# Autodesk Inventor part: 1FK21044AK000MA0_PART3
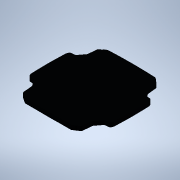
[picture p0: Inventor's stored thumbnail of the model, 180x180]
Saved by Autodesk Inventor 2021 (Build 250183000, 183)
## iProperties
Created: 2025-04
Part Number: 1FK21044AK000MA0_PART3
Material: Generic
Catalog Web Link: www.3dfindit.com
Description: -Servo synchronous motor
Document SubType Name: Modeling
Designer: psAdmin
Mass: 21.7019 g
Surface Area: 120.085 cm^2
Volume: 21.7019 cm^3
Density: 1 g/cm^3
Appearance: PSOLRGB-38-46-56
Category: PARTsolutions
Title: 1FK21044AK000MA0_PART3
Author: Cadenas PARTsolutions
Comments: Servo synchronous motor
Sending System: PARTsolutions
Preprocessor: ST-DEVELOPER v19.3
PSOL_IDENT_0: {$CADENAS_DATA/23d-libs/siemens_ag/_cat_/87/f4/1fk21044ak000ma0.prj},213 {VTYP=3D},{NB=1FK21044AK000
PSOL_IDENT_1: MA0_PART3},{LINA=1FK21044AK000MA0_PART3},{NN=1FK21044AK000MA0_PART3},{NOPRJ=TRUE},{DATE=19.08.2025 1
PSOL_IDENT_2: 4:00:48},{GEOMDATE=30.07.2025 02:00:50},{VERSION=},{LINEID=10},{WBVAR=},{WBNUMERIC=}  {NB=1FK21044AK
PSOL_IDENT_3: 000MA0_PART3},{LINA=1FK21044AK000MA0_PART3},{KT=DUMMY},{PREVIEW=../../../_pool_/cb/72/p_d211_xx_0043
PSOL_IDENT_4: 4j.png},{DESCSHORT=SIMOTICS S-1FK2 HD, SINAMICS S210 3AC 400V-480V, 0.95 Nm, 6000 rpm},{DESCLONG=SIM
PSOL_IDENT_5: OTICS S-1FK2 HD servo motor M0=1.27 Nm; PN = 0.6 kW at nN=6000 rpm (380-480 V); PN = 0.4 kW at nN=30
PSOL_IDENT_6: 00 rpm (200-240 V); degree of protection IP64; cylindrical shaft D19x40mm; absolute encoder 22-bit +
PSOL_IDENT_7: 12-bit multiturn (encoder AM22DQC); with OCC interface; plug size M17, rotatable; SIMOTICS S-1FK2 s
PSOL_IDENT_8: ervomotorfor a wide range of uses in industrial environments. SIMOTICS S‑1FK2 servomotors are compac
PSOL_IDENT_9: t synchronous motors with a high dynamic performance that set themselves apart as a result of their
PSOL_IDENT_10: high power density, degree of protection and overload capability. The motors are available in two va
PSOL_IDENT_11: riants: as High Dynamic variant (highest dynamic performance as a result of the low intrinsic moment
PSOL_IDENT_12: of inertia for applications demanding a high dynamic performance with low moved masses) - and as Co
PSOL_IDENT_13: mpact variant (precise and stable closed-loop control for medium up to large moved masses as a resul
PSOL_IDENT_14: t of a medium intrinsic moment of inertia). SIMOTICSS‑1FK2 servomotors fully exploit their strengths
PSOL_IDENT_15: in a system with the SINAMICSS210 frequency converter and simple connection using the one cable con
PSOL_IDENT_16: nection (OCC). Advantages include the short control and positioning times, fast and precise correcti
PSOL_IDENT_17: on of disturbing quantities as well as stable control with a high dynamic performance. The servo mot
PSOL_IDENT_18: ors can be configured to address a wide range of requirements. For example with and without holding
PSOL_IDENT_19: brake, IP64 or IP65 degree of protection, singleturn or multiturn absolute encoders - to name just a
PSOL_IDENT_20: few. Further, the servomotors are available in different shaft heights extending from 20 to 100. A
PSOL_IDENT_21: shaft sealing ring is available to achieve an IP65 degree of protection and for subsequent mounting
PSOL_IDENT_22: at the motor or as spare part. SIMOTICS - the optimum motor for each and every motion control applic
PSOL_IDENT_23: ation.},{INTNO=195125056312},{SUPPLIERALTNO=1FK2104-4AK00-0MA0},{MANUID=1FK21044AK000MA0},{MANUNAME=
PSOL_IDENT_24: Siemens},{MANUTYPEDESC=Synchronous motor 1FK2-HD 1,27 Nm},{AAU732=SIMOTICS},{AAO057=S-1FK2},{AAU734=
PSOL_IDENT_25: SIMOTICS S-1FK2 HD servo motor M0=1.27 Nm; PN = 0.6 kW at nN=6000 rpm (380-480 V); PN = 0.4 kW at nN=
PSOL_IDENT_26: 3000 rpm (200-240 V); degree of protection IP64; cylindrical shaft D19x40mm; absolute encoder 22-bit
PSOL_IDENT_27: + 12-bit multiturn (encoder AM22DQC); with OCC interface; plug size M17, rotatable;},{AAW338=Synchr
PSOL_IDENT_28: onous motor 1FK2-HD 1,27 Nm},{AAO742=SIMOTICS},{AAO663=4042948690994},{NOCUPEROU=1},{PRICEQUANTITY=1
PSOL_IDENT_29: },{QUANTITYMIN=1},{QUANTITYINT=1},{CTN=85015100},{COO=DE},{AAO676=1FK2104-4AK00-0MA0},{AAO677=Siemen
PSOL_IDENT_30: s AG},{ORDERUNIT=C62},{CONTENTUNIT=C62}
NB: 1FK21044AK000MA0_PART3
NT: Servo synchronous motor
NBSYN: $MANUID._PART3
LINA: 1FK21044AK000MA0_PART3
CATALOG: SIEMENS
PREVIEW: ../../../_pool_/cb/72/p_d211_xx_00434j.png
DESCSHORT: SIMOTICS S-1FK2 HD, SINAMICS S210 3AC 400V-480V, 0.95 Nm, 6000 rpm
DESCLONG: SIMOTICS S-1FK2 HD servo motor M0=1.27 Nm; PN = 0.6 kW at nN=6000 rpm (380-480 V); PN = 0.4 kW at nN=3000 rpm (200-240 V); degree of protection IP64; cylindrica
INTNO: 195125056312
SUPPLIERALTNO: 1FK2104-4AK00-0MA0
MANUID: 1FK21044AK000MA0
MANUNAME: Siemens
MANUTYPEDESC: Synchronous motor 1FK2-HD 1,27 Nm
AAU732: SIMOTICS
AAO057: S-1FK2
AAU734: SIMOTICS S-1FK2 HD servo motor M0=1.27 Nm; PN = 0.6 kW at nN=6000 rpm (380-480 V); PN = 0.4 kW at nN=3000 rpm (200-240 V); degree of protection IP64; cylindrica
AAW338: Synchronous motor 1FK2-HD 1,27 Nm
AAO742: SIMOTICS
AAO663: 4042948690994.0
NOCUPEROU: 1
PRICEQUANTITY: 1
QUANTITYMIN: 1
QUANTITYINT: 1
CTN: 85015100
COO: DE
ARTICLENO: 1FK21044AK000MA0_PART3
BOMINFO: 1FK21044AK000MA0_PART3
CREATOR: CADENAS GmbH
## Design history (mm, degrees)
feature "2025_04_17_15_37_40_0494"
body "Solid1"
